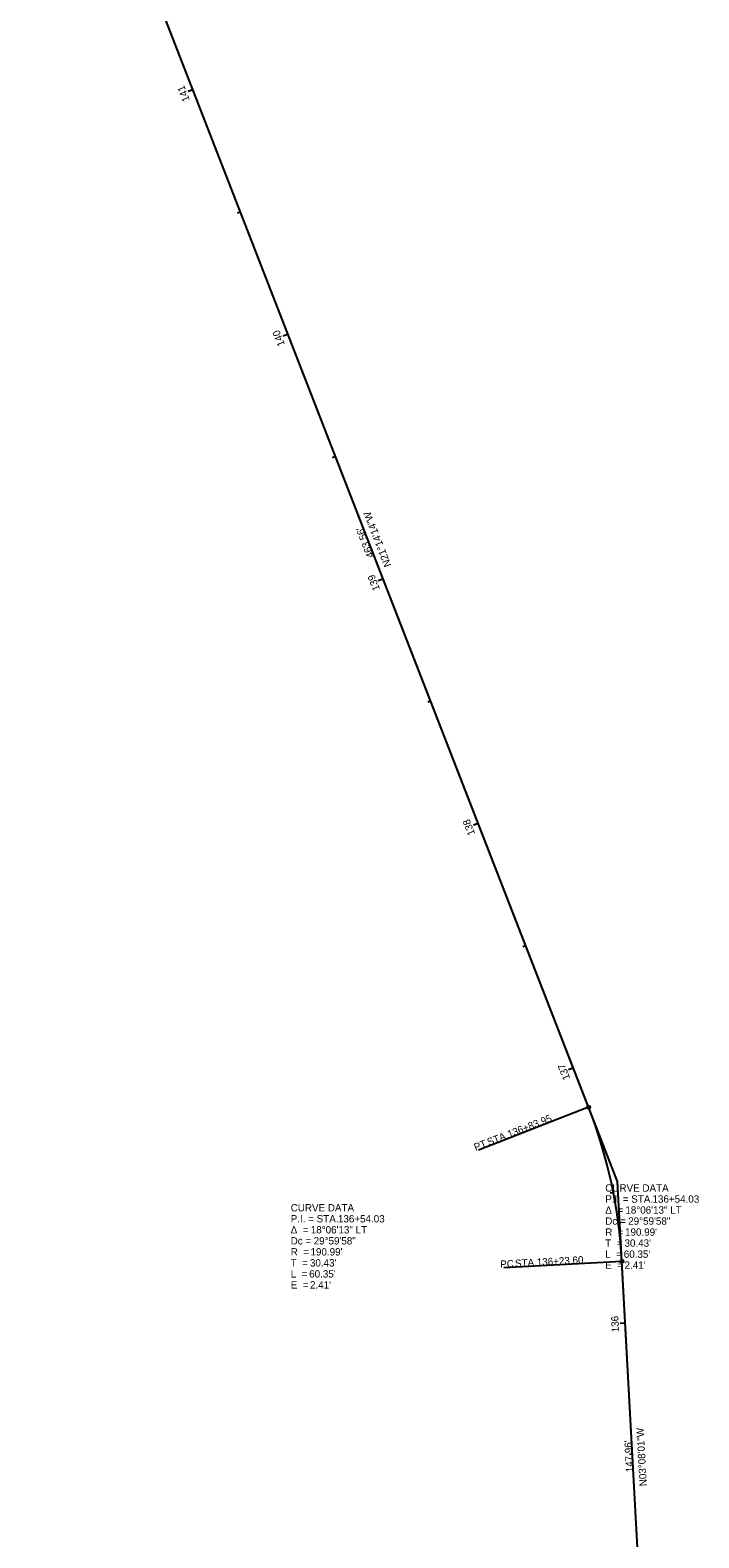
# Model space of a CAD drawing. Extents: x 177110 to 177558, y 286252 to 294117.
# Drawn here: x 177303 to 177558, y 289293 to 289868 of the extents above; entities that cross this region are included whole.
import ezdxf

# ---------------------------------------------------------------- set-up
doc = ezdxf.new("R2010")
doc.units = 0
for name, color, linetype in [('GE_X_Alignment_500_Bearings', 7, 'Continuous'), ('GE_X_Alignment_500_Cardinal_Points', 7, 'Continuous'), ('GE_X_Alignment_500_Curve_Data', 7, 'Continuous'), ('GE_X_Alignment_500_Distances', 7, 'Continuous'), ('GE_X_Alignment_500_Stations', 7, 'Continuous'), ('RW_X_CL', 7, 'Continuous'), ('RW_X_CL_100_Bearings', 7, 'Continuous'), ('RW_X_CL_100_Cardinal_Points', 7, 'Continuous'), ('RW_X_CL_100_Curve_Data', 7, 'Continuous'), ('RW_X_CL_100_Distances', 7, 'Continuous'), ('RW_X_CL_100_Stations', 7, 'Continuous'), ('SC_Scratch1', 7, 'Continuous')]:
    doc.layers.add(name, color=color, linetype=linetype)

msp = doc.modelspace()

# ---------------------------------------------------------------- linework, layer by layer
at = {"layer": 'GE_X_Alignment_500_Cardinal_Points'}
for p, q in [((177516.14, 289457.09), (177474.19, 289440.79)), ((177528.82, 289398.35), (177483.89, 289395.89))]:
    msp.add_line(p, q, dxfattribs=at)
for centre in [(177516.14, 289457.09), (177528.82, 289398.35)]:
    msp.add_circle(centre, 0.6, dxfattribs=at)
at = {"layer": 'GE_X_Alignment_500_Stations'}
for p, q in [((177365.43, 289844.89), (177364.31, 289844.45)), ((177401.66, 289751.68), (177399.79, 289750.96)), ((177437.88, 289658.47), (177436.76, 289658.04)), ((177474.1, 289565.26), (177472.98, 289564.83)), ((177510.32, 289472.05), (177509.21, 289471.62)), ((177530.11, 289374.78), (177528.91, 289374.72))]:
    msp.add_line(p, q, dxfattribs=at)
at = {"layer": 'RW_X_CL'}
for p, q in [((177516.14, 289457.09), (177348.22, 289889.17)), ((177536.91, 289250.62), (177528.82, 289398.35))]:
    msp.add_line(p, q, dxfattribs=at)
msp.add_arc((177338.12, 289387.91), 190.99, 3.13348, 21.23721, dxfattribs=at)
at = {"layer": 'RW_X_CL_100_Cardinal_Points'}
for p, q in [((177516.14, 289457.09), (177474.19, 289440.79)), ((177528.82, 289398.35), (177483.89, 289395.89))]:
    msp.add_line(p, q, dxfattribs=at)
for centre in [(177516.14, 289457.09), (177528.82, 289398.35)]:
    msp.add_circle(centre, 0.6, dxfattribs=at)
at = {"layer": 'RW_X_CL_100_Stations'}
for p, q in [((177365.43, 289844.89), (177363.57, 289844.16)), ((177383.54, 289798.28), (177382.43, 289797.85)), ((177401.66, 289751.68), (177399.79, 289750.96)), ((177419.77, 289705.08), (177418.65, 289704.64)), ((177437.88, 289658.47), (177436.01, 289657.75)), ((177455.99, 289611.87), (177454.87, 289611.43)), ((177474.1, 289565.26), (177472.24, 289564.54)), ((177492.21, 289518.66), (177491.09, 289518.22)), ((177510.32, 289472.05), (177508.46, 289471.33)), ((177525.57, 289424.52), (177524.39, 289424.29)), ((177530.11, 289374.78), (177528.12, 289374.67)), ((177532.85, 289324.86), (177531.65, 289324.79))]:
    msp.add_line(p, q, dxfattribs=at)
at = {"layer": 'SC_Scratch1'}
for p, q in [((177527.16, 289428.73), (177303.45, 290004.39)), ((177542.29, 289152.38), (177527.16, 289428.73))]:
    msp.add_line(p, q, dxfattribs=at)
msp.add_arc((177338.12, 289387.91), 190.99, 3.13348, 21.23721, dxfattribs=at)

# ---------------------------------------------------------------- texts
at = {"layer": 'GE_X_Alignment_500_Bearings'}
for s, rotation, p in [('N21°14\'14"W', 111.23721, (177441.01, 289663.66)), ('N03°08\'01"W', 93.13348, (177538.32, 289312.73))]:
    msp.add_text(s, height=2.8, rotation=rotation, dxfattribs=at).set_placement(p)
at = {"layer": 'GE_X_Alignment_500_Cardinal_Points'}
for s, rotation, p in [('136+83.95', 21.23721, (177485.85, 289445.36)), ('PT', 21.23721, (177473.11, 289440.41)), (' STA. ', 21.23721, (177477.16, 289441.99)), ('PC', 3.13348, (177482.55, 289395.86)), (' STA. ', 3.13348, (177487.15, 289396.11)), ('136+23.60', 3.13348, (177496.46, 289396.62))]:
    msp.add_text(s, height=2.8, rotation=rotation, dxfattribs=at).set_placement(p)
at = {"layer": 'GE_X_Alignment_500_Curve_Data'}
for s, p in [('CURVE DATA', (177522.48, 289424.92)), ('P.I. = STA. ', (177522.48, 289420.72)), ('136+54.03', (177540.47, 289420.72)), ('Δ  = ', (177522.48, 289416.52)), ('18°06\'13" LT', (177530.13, 289416.52)), ('Dc = ', (177522.48, 289412.32)), ('R  = ', (177522.48, 289408.12)), ("190.99'", (177530.01, 289408.12)), ('29°59\'58"', (177531.22, 289412.32)), ('T  = ', (177522.48, 289403.92)), ("30.43'", (177529.8, 289403.92)), ('L  = ', (177522.48, 289399.72)), ('E  = ', (177522.48, 289395.52)), ("60.35'", (177529.52, 289399.72)), ("2.41'", (177529.82, 289395.52))]:
    msp.add_text(s, height=2.8, dxfattribs=at).set_placement(p)
at = {"layer": 'GE_X_Alignment_500_Distances'}
for s, rotation, p in [("463.56'", 111.23721, (177434.48, 289667.12)), ("147.96'", 93.13348, (177533.18, 289318.05))]:
    msp.add_text(s, height=2.8, rotation=rotation, dxfattribs=at).set_placement(p)
at = {"layer": 'GE_X_Alignment_500_Stations'}
msp.add_text('140', height=2.8, rotation=111.23721, dxfattribs=at).set_placement((177400.51, 289747.73))
at = {"layer": 'RW_X_CL_100_Bearings'}
for s, rotation, p in [('N21°14\'14"W', 111.23721, (177441.01, 289663.66)), ('N03°08\'01"W', 93.13348, (177538.32, 289312.73))]:
    msp.add_text(s, height=2.8, rotation=rotation, dxfattribs=at).set_placement(p)
at = {"layer": 'RW_X_CL_100_Cardinal_Points'}
for s, rotation, p in [('136+83.95', 21.23721, (177485.85, 289445.36)), ('PT', 21.23721, (177473.11, 289440.41)), (' STA. ', 21.23721, (177477.16, 289441.99)), ('PC', 3.13348, (177482.55, 289395.86)), (' STA. ', 3.13348, (177487.15, 289396.11)), ('136+23.60', 3.13348, (177496.46, 289396.62))]:
    msp.add_text(s, height=2.8, rotation=rotation, dxfattribs=at).set_placement(p)
at = {"layer": 'RW_X_CL_100_Curve_Data'}
for s, p in [('CURVE DATA', (177402.67, 289417.39)), ('P.I. = STA. ', (177402.67, 289413.19)), ('136+54.03', (177420.66, 289413.19)), ('Δ  = ', (177402.67, 289408.99)), ('18°06\'13" LT', (177410.32, 289408.99)), ('Dc = ', (177402.67, 289404.79)), ('29°59\'58"', (177411.42, 289404.79)), ('T  = ', (177402.67, 289396.39)), ('R  = ', (177402.67, 289400.59)), ("30.43'", (177409.99, 289396.39)), ("190.99'", (177410.21, 289400.59)), ('L  = ', (177402.67, 289392.19)), ("60.35'", (177409.71, 289392.19)), ('E  = ', (177402.67, 289387.99)), ("2.41'", (177410.02, 289387.99))]:
    msp.add_text(s, height=2.8, dxfattribs=at).set_placement(p)
at = {"layer": 'RW_X_CL_100_Distances'}
for s, rotation, p in [("463.56'", 111.23721, (177434.48, 289667.12)), ("147.96'", 93.13348, (177533.18, 289318.05))]:
    msp.add_text(s, height=2.8, rotation=rotation, dxfattribs=at).set_placement(p)
at = {"layer": 'RW_X_CL_100_Stations'}
for s, rotation, p in [('141', 111.23721, (177364.27, 289840.98)), ('140', 111.23721, (177400.51, 289747.73)), ('139', 111.23721, (177436.72, 289654.56)), ('138', 111.23721, (177472.95, 289561.33)), ('137', 111.23721, (177509.17, 289468.12)), ('136', 93.13348, (177527.79, 289371.4))]:
    msp.add_text(s, height=2.8, rotation=rotation, dxfattribs=at).set_placement(p)

doc.saveas('drawing.dxf')
